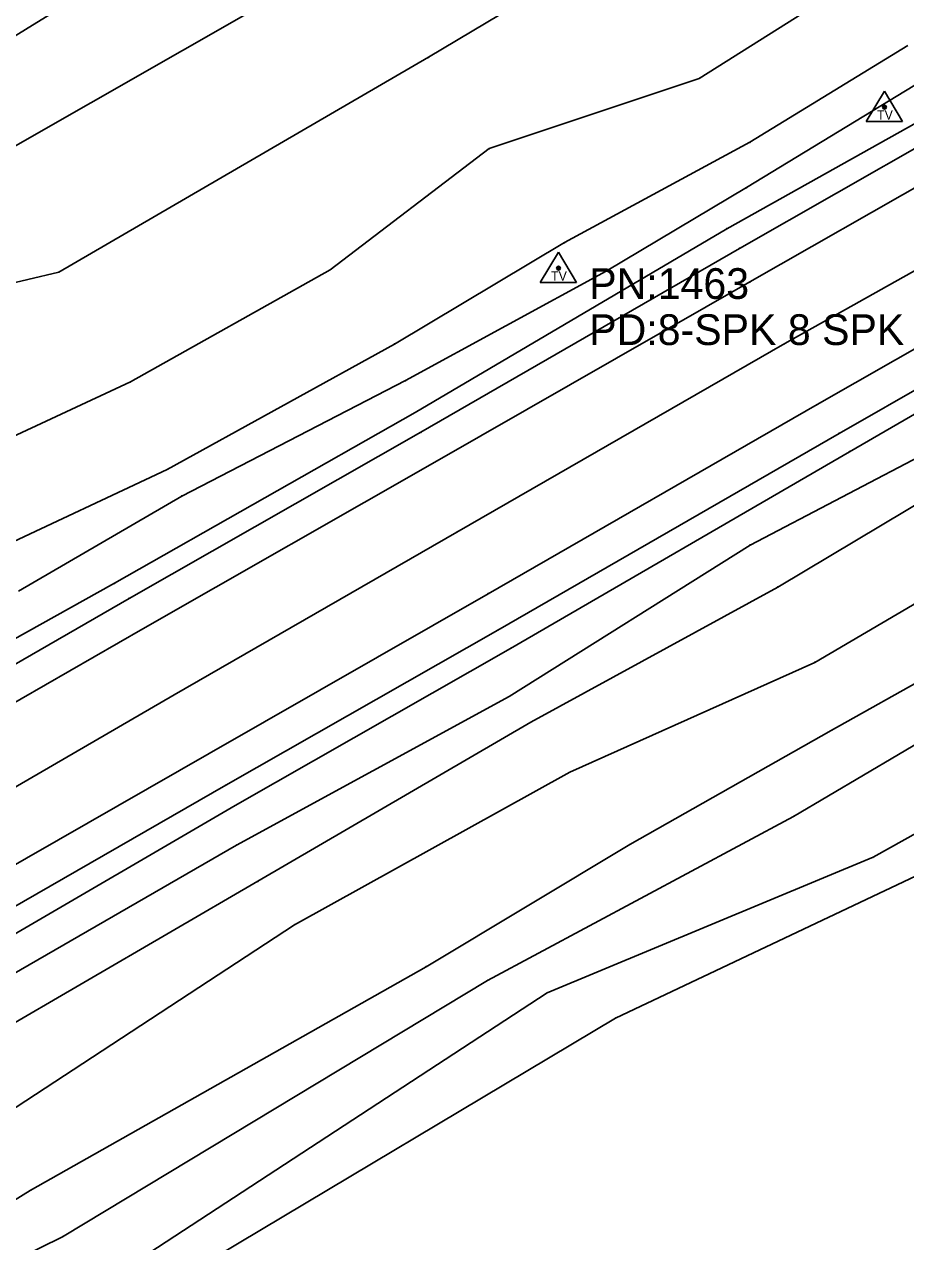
# Model space of a CAD drawing. Extents: x 1419505 to 1434054, y 1956910 to 1968644.
# Drawn here: x 1422395.6 to 1422539.1, y 1958500.2 to 1958698.2 of the extents above; entities that cross this region are included whole.
import ezdxf

# ---------------------------------------------------------------- set-up
doc = ezdxf.new("R2010")
doc.units = 0
for name, color, linetype in [('S_BREAKLINE', 7, 'Continuous'), ('S_DITCHLINE', 7, 'Continuous'), ('S_EDGE_PAVEMENT', 7, 'Continuous'), ('S_GRD_PT_SYM', 7, 'Continuous'), ('S_PAVEMENT_CROWN', 7, 'Continuous'), ('S_RDW_PT_SYM', 7, 'Continuous'), ('S_SECONDARY_CTL', 7, 'Continuous'), ('S_SECONDARY_CTL_ANNOT', 7, 'Continuous'), ('S_SHOULDER', 7, 'Continuous')]:
    doc.layers.add(name, color=color, linetype=linetype)

msp = doc.modelspace()

# ---------------------------------------------------------------- linework, layer by layer
at = {"layer": 'S_BREAKLINE'}
for p, q in [((1422382.7101, 1958689.3782), (1422441.0538, 1958725.3215)), ((1422461.4141, 1958692.8994), (1422515.4536, 1958725.2285)), ((1422390.1545, 1958676.2194), (1422450.1924, 1958710.4926)), ((1422505.461, 1958689.4512), (1422526.6403, 1958702.7961)), ((1422513.7285, 1958679.0625), (1422539.4222, 1958694.7976)), ((1422401.2202, 1958657.9362), (1422461.4141, 1958692.8994)), ((1422509.9403, 1958664.9946), (1422557.0843, 1958691.3403)), ((1422471.2908, 1958678.0405), (1422505.461, 1958689.4512)), ((1422513.1865, 1958671.6841), (1422541.8283, 1958689.1252)), ((1422445.4121, 1958658.3022), (1422471.2908, 1958678.0405)), ((1422483.5336, 1958662.7245), (1422513.7285, 1958679.0625)), ((1422490.309, 1958658.1032), (1422513.1865, 1958671.6841)), ((1422459.229, 1958635.0887), (1422509.9403, 1958664.9946)), ((1422455.8438, 1958646.2244), (1422483.5336, 1958662.7245)), ((1422359.4856, 1958648.0975), (1422401.2202, 1958657.9362)), ((1422412.872, 1958640.073), (1422445.4121, 1958658.3022)), ((1422457.6589, 1958640.283), (1422490.309, 1958658.1032)), ((1422529.9036, 1958628.7053), (1422575.9995, 1958655.405)), ((1422418.8514, 1958625.8221), (1422455.8438, 1958646.2244)), ((1422376.8577, 1958623.2629), (1422412.872, 1958640.073)), ((1422421.2215, 1958621.4938), (1422457.6589, 1958640.283)), ((1422513.7555, 1958613.5103), (1422560.7295, 1958638.1109)), ((1422410.3008, 1958607.2949), (1422459.229, 1958635.0887)), ((1422518.2358, 1958606.6839), (1422563.0037, 1958633.3846)), ((1422474.764, 1958596.7022), (1422529.9036, 1958628.7053)), ((1422391.0466, 1958612.7583), (1422418.8514, 1958625.8221)), ((1422524.2652, 1958594.4251), (1422575.5835, 1958624.449)), ((1422394.6328, 1958606.0288), (1422421.2215, 1958621.4938)), ((1422526.9554, 1958583.3564), (1422582.2199, 1958614.3194)), ((1422474.546, 1958588.8787), (1422513.7555, 1958613.5103)), ((1422359.4726, 1958579.0301), (1422410.3008, 1958607.2949)), ((1422478.0582, 1958584.6984), (1422518.2358, 1958606.6839)), ((1422429.9161, 1958571.1386), (1422474.764, 1958596.7022)), ((1422484.3896, 1958576.5599), (1422524.2652, 1958594.4251)), ((1422430.1541, 1958564.6961), (1422474.546, 1958588.8787)), ((1422433.6193, 1958558.8038), (1422478.0582, 1958584.6984)), ((1422494.1883, 1958564.8072), (1422526.9554, 1958583.3564)), ((1422439.6027, 1958551.7483), (1422484.3896, 1958576.5599)), ((1422379.5428, 1958541.7597), (1422429.9161, 1958571.1386)), ((1422376.5187, 1958533.7862), (1422430.1541, 1958564.6961)), ((1422460.9871, 1958544.9109), (1422494.1883, 1958564.8072)), ((1422379.8909, 1958527.5858), (1422433.6193, 1958558.8038)), ((1422491.8421, 1958536.5513), (1422540.7583, 1958559.6738)), ((1422386.7113, 1958517.1431), (1422439.6027, 1958551.7483)), ((1422396.5669, 1958508.5065), (1422460.9871, 1958544.9109)), ((1422413.8181, 1958490.0183), (1422491.8421, 1958536.5513)), ((1422351.098, 1958480.5897), (1422396.5669, 1958508.5065))]:
    msp.add_line(p, q, dxfattribs=at)
at = {"layer": 'S_DITCHLINE'}
for p, q in [((1422520.832, 1958569.3745), (1422586.0932, 1958607.8579)), ((1422533.7638, 1958562.71), (1422593.1296, 1958595.9822)), ((1422471.0038, 1958542.6787), (1422520.832, 1958569.3745)), ((1422480.6964, 1958540.6546), (1422533.7638, 1958562.71)), ((1422401.8303, 1958500.98), (1422471.0038, 1958542.6787)), ((1422409.7558, 1958494.3216), (1422480.6964, 1958540.6546)), ((1422352.3031, 1958476.6255), (1422401.8303, 1958500.98))]:
    msp.add_line(p, q, dxfattribs=at)
at = {"layer": 'S_EDGE_PAVEMENT'}
for p, q in [((1422513.7115, 1958656.3271), (1422561.5106, 1958683.6458)), ((1422524.6412, 1958636.3678), (1422571.3862, 1958663.0315)), ((1422462.8152, 1958627.2262), (1422513.7115, 1958656.3271)), ((1422471.0978, 1958605.5868), (1422524.6412, 1958636.3678)), ((1422414.9011, 1958599.8904), (1422462.8152, 1958627.2262)), ((1422425.6748, 1958579.5971), (1422471.0978, 1958605.5868)), ((1422363.2818, 1958570.2055), (1422414.9011, 1958599.8904)), ((1422374.5395, 1958550.3272), (1422425.6748, 1958579.5971))]:
    msp.add_line(p, q, dxfattribs=at)
at = {"layer": 'S_GRD_PT_SYM'}
for points in [[(1422461.4141, 1958692.8994), (1422461.4141, 1958692.9494), (1422461.4141, 1958692.8994), (1422461.3641, 1958692.8994), (1422461.4141, 1958692.8994), (1422461.4141, 1958692.8494), (1422461.4141, 1958692.8994), (1422461.4641, 1958692.8994)], [(1422505.461, 1958689.4512), (1422505.461, 1958689.5012), (1422505.461, 1958689.4512), (1422505.411, 1958689.4512), (1422505.461, 1958689.4512), (1422505.461, 1958689.4012), (1422505.461, 1958689.4512), (1422505.511, 1958689.4512)], [(1422471.2908, 1958678.0405), (1422471.2908, 1958678.0905), (1422471.2908, 1958678.0405), (1422471.2408, 1958678.0405), (1422471.2908, 1958678.0405), (1422471.2908, 1958677.9905), (1422471.2908, 1958678.0405), (1422471.3408, 1958678.0405)], [(1422513.7285, 1958679.0625), (1422513.7285, 1958679.1125), (1422513.7285, 1958679.0625), (1422513.6785, 1958679.0625), (1422513.7285, 1958679.0625), (1422513.7285, 1958679.0125), (1422513.7285, 1958679.0625), (1422513.7785, 1958679.0625)], [(1422513.1865, 1958671.6841), (1422513.1865, 1958671.7341), (1422513.1865, 1958671.6841), (1422513.1365, 1958671.6841), (1422513.1865, 1958671.6841), (1422513.1865, 1958671.6341), (1422513.1865, 1958671.6841), (1422513.2365, 1958671.6841)], [(1422509.9403, 1958664.9946), (1422509.9403, 1958665.0446), (1422509.9403, 1958664.9946), (1422509.8903, 1958664.9946), (1422509.9403, 1958664.9946), (1422509.9403, 1958664.9446), (1422509.9403, 1958664.9946), (1422509.9903, 1958664.9946)], [(1422483.5336, 1958662.7245), (1422483.5336, 1958662.7745), (1422483.5336, 1958662.7245), (1422483.4836, 1958662.7245), (1422483.5336, 1958662.7245), (1422483.5336, 1958662.6745), (1422483.5336, 1958662.7245), (1422483.5836, 1958662.7245)], [(1422401.2202, 1958657.9362), (1422401.2202, 1958657.9862), (1422401.2202, 1958657.9362), (1422401.1702, 1958657.9362), (1422401.2202, 1958657.9362), (1422401.2202, 1958657.8862), (1422401.2202, 1958657.9362), (1422401.2702, 1958657.9362)], [(1422445.4121, 1958658.3022), (1422445.4121, 1958658.3522), (1422445.4121, 1958658.3022), (1422445.3621, 1958658.3022), (1422445.4121, 1958658.3022), (1422445.4121, 1958658.2522), (1422445.4121, 1958658.3022), (1422445.4621, 1958658.3022)], [(1422490.309, 1958658.1032), (1422490.309, 1958658.1532), (1422490.309, 1958658.1032), (1422490.259, 1958658.1032), (1422490.309, 1958658.1032), (1422490.309, 1958658.0532), (1422490.309, 1958658.1032), (1422490.359, 1958658.1032)], [(1422455.8438, 1958646.2244), (1422455.8438, 1958646.2744), (1422455.8438, 1958646.2244), (1422455.7938, 1958646.2244), (1422455.8438, 1958646.2244), (1422455.8438, 1958646.1744), (1422455.8438, 1958646.2244), (1422455.8938, 1958646.2244)], [(1422412.872, 1958640.073), (1422412.872, 1958640.123), (1422412.872, 1958640.073), (1422412.822, 1958640.073), (1422412.872, 1958640.073), (1422412.872, 1958640.023), (1422412.872, 1958640.073), (1422412.922, 1958640.073)], [(1422457.6589, 1958640.283), (1422457.6589, 1958640.333), (1422457.6589, 1958640.283), (1422457.6089, 1958640.283), (1422457.6589, 1958640.283), (1422457.6589, 1958640.233), (1422457.6589, 1958640.283), (1422457.7089, 1958640.283)], [(1422459.229, 1958635.0887), (1422459.229, 1958635.1387), (1422459.229, 1958635.0887), (1422459.179, 1958635.0887), (1422459.229, 1958635.0887), (1422459.229, 1958635.0387), (1422459.229, 1958635.0887), (1422459.279, 1958635.0887)], [(1422529.9036, 1958628.7053), (1422529.9036, 1958628.7553), (1422529.9036, 1958628.7053), (1422529.8536, 1958628.7053), (1422529.9036, 1958628.7053), (1422529.9036, 1958628.6553), (1422529.9036, 1958628.7053), (1422529.9536, 1958628.7053)], [(1422418.8514, 1958625.8221), (1422418.8514, 1958625.8721), (1422418.8514, 1958625.8221), (1422418.8014, 1958625.8221), (1422418.8514, 1958625.8221), (1422418.8514, 1958625.7721), (1422418.8514, 1958625.8221), (1422418.9014, 1958625.8221)], [(1422421.2215, 1958621.4938), (1422421.2215, 1958621.5438), (1422421.2215, 1958621.4938), (1422421.1715, 1958621.4938), (1422421.2215, 1958621.4938), (1422421.2215, 1958621.4438), (1422421.2215, 1958621.4938), (1422421.2715, 1958621.4938)], [(1422513.7555, 1958613.5103), (1422513.7555, 1958613.5603), (1422513.7555, 1958613.5103), (1422513.7055, 1958613.5103), (1422513.7555, 1958613.5103), (1422513.7555, 1958613.4603), (1422513.7555, 1958613.5103), (1422513.8055, 1958613.5103)], [(1422410.3008, 1958607.2949), (1422410.3008, 1958607.3449), (1422410.3008, 1958607.2949), (1422410.2508, 1958607.2949), (1422410.3008, 1958607.2949), (1422410.3008, 1958607.2449), (1422410.3008, 1958607.2949), (1422410.3508, 1958607.2949)], [(1422518.2358, 1958606.6839), (1422518.2358, 1958606.7339), (1422518.2358, 1958606.6839), (1422518.1858, 1958606.6839), (1422518.2358, 1958606.6839), (1422518.2358, 1958606.6339), (1422518.2358, 1958606.6839), (1422518.2858, 1958606.6839)], [(1422474.764, 1958596.7022), (1422474.764, 1958596.7522), (1422474.764, 1958596.7022), (1422474.714, 1958596.7022), (1422474.764, 1958596.7022), (1422474.764, 1958596.6522), (1422474.764, 1958596.7022), (1422474.814, 1958596.7022)], [(1422524.2652, 1958594.4251), (1422524.2652, 1958594.4751), (1422524.2652, 1958594.4251), (1422524.2152, 1958594.4251), (1422524.2652, 1958594.4251), (1422524.2652, 1958594.3751), (1422524.2652, 1958594.4251), (1422524.3152, 1958594.4251)], [(1422474.546, 1958588.8787), (1422474.546, 1958588.9287), (1422474.546, 1958588.8787), (1422474.496, 1958588.8787), (1422474.546, 1958588.8787), (1422474.546, 1958588.8287), (1422474.546, 1958588.8787), (1422474.596, 1958588.8787)], [(1422478.0582, 1958584.6984), (1422478.0582, 1958584.7484), (1422478.0582, 1958584.6984), (1422478.0082, 1958584.6984), (1422478.0582, 1958584.6984), (1422478.0582, 1958584.6484), (1422478.0582, 1958584.6984), (1422478.1082, 1958584.6984)], [(1422526.9554, 1958583.3564), (1422526.9554, 1958583.4064), (1422526.9554, 1958583.3564), (1422526.9054, 1958583.3564), (1422526.9554, 1958583.3564), (1422526.9554, 1958583.3064), (1422526.9554, 1958583.3564), (1422527.0054, 1958583.3564)], [(1422484.3896, 1958576.5599), (1422484.3896, 1958576.6099), (1422484.3896, 1958576.5599), (1422484.3396, 1958576.5599), (1422484.3896, 1958576.5599), (1422484.3896, 1958576.5099), (1422484.3896, 1958576.5599), (1422484.4396, 1958576.5599)], [(1422429.9161, 1958571.1386), (1422429.9161, 1958571.1886), (1422429.9161, 1958571.1386), (1422429.8661, 1958571.1386), (1422429.9161, 1958571.1386), (1422429.9161, 1958571.0886), (1422429.9161, 1958571.1386), (1422429.9661, 1958571.1386)], [(1422520.832, 1958569.3745), (1422520.832, 1958569.4245), (1422520.832, 1958569.3745), (1422520.782, 1958569.3745), (1422520.832, 1958569.3745), (1422520.832, 1958569.3245), (1422520.832, 1958569.3745), (1422520.882, 1958569.3745)], [(1422430.1541, 1958564.6961), (1422430.1541, 1958564.7461), (1422430.1541, 1958564.6961), (1422430.1041, 1958564.6961), (1422430.1541, 1958564.6961), (1422430.1541, 1958564.6461), (1422430.1541, 1958564.6961), (1422430.2041, 1958564.6961)], [(1422494.1883, 1958564.8072), (1422494.1883, 1958564.8572), (1422494.1883, 1958564.8072), (1422494.1383, 1958564.8072), (1422494.1883, 1958564.8072), (1422494.1883, 1958564.7572), (1422494.1883, 1958564.8072), (1422494.2383, 1958564.8072)], [(1422533.7638, 1958562.71), (1422533.7638, 1958562.76), (1422533.7638, 1958562.71), (1422533.7138, 1958562.71), (1422533.7638, 1958562.71), (1422533.7638, 1958562.66), (1422533.7638, 1958562.71), (1422533.8138, 1958562.71)], [(1422433.6193, 1958558.8038), (1422433.6193, 1958558.8538), (1422433.6193, 1958558.8038), (1422433.5693, 1958558.8038), (1422433.6193, 1958558.8038), (1422433.6193, 1958558.7538), (1422433.6193, 1958558.8038), (1422433.6693, 1958558.8038)], [(1422439.6027, 1958551.7483), (1422439.6027, 1958551.7983), (1422439.6027, 1958551.7483), (1422439.5527, 1958551.7483), (1422439.6027, 1958551.7483), (1422439.6027, 1958551.6983), (1422439.6027, 1958551.7483), (1422439.6527, 1958551.7483)], [(1422460.9871, 1958544.9109), (1422460.9871, 1958544.9609), (1422460.9871, 1958544.9109), (1422460.9371, 1958544.9109), (1422460.9871, 1958544.9109), (1422460.9871, 1958544.8609), (1422460.9871, 1958544.9109), (1422461.0371, 1958544.9109)], [(1422471.0038, 1958542.6787), (1422471.0038, 1958542.7287), (1422471.0038, 1958542.6787), (1422470.9538, 1958542.6787), (1422471.0038, 1958542.6787), (1422471.0038, 1958542.6287), (1422471.0038, 1958542.6787), (1422471.0538, 1958542.6787)], [(1422480.6964, 1958540.6546), (1422480.6964, 1958540.7046), (1422480.6964, 1958540.6546), (1422480.6464, 1958540.6546), (1422480.6964, 1958540.6546), (1422480.6964, 1958540.6046), (1422480.6964, 1958540.6546), (1422480.7464, 1958540.6546)], [(1422491.8421, 1958536.5513), (1422491.8421, 1958536.6013), (1422491.8421, 1958536.5513), (1422491.7921, 1958536.5513), (1422491.8421, 1958536.5513), (1422491.8421, 1958536.5013), (1422491.8421, 1958536.5513), (1422491.8921, 1958536.5513)], [(1422396.5669, 1958508.5065), (1422396.5669, 1958508.5565), (1422396.5669, 1958508.5065), (1422396.5169, 1958508.5065), (1422396.5669, 1958508.5065), (1422396.5669, 1958508.4565), (1422396.5669, 1958508.5065), (1422396.6169, 1958508.5065)], [(1422401.8303, 1958500.98), (1422401.8303, 1958501.03), (1422401.8303, 1958500.98), (1422401.7803, 1958500.98), (1422401.8303, 1958500.98), (1422401.8303, 1958500.93), (1422401.8303, 1958500.98), (1422401.8803, 1958500.98)]]:
    msp.add_lwpolyline(points, dxfattribs=at)
at = {"layer": 'S_PAVEMENT_CROWN'}
for p, q in [((1422519.3899, 1958646.2924), (1422565.7189, 1958672.3091)), ((1422466.0314, 1958615.6224), (1422519.3899, 1958646.2924)), ((1422419.9995, 1958589.1487), (1422466.0314, 1958615.6224)), ((1422369.2062, 1958559.7138), (1422419.9995, 1958589.1487))]:
    msp.add_line(p, q, dxfattribs=at)
at = {"layer": 'S_RDW_PT_SYM'}
for points in [[(1422512.0114, 1958661.7954), (1422512.0114, 1958661.8454), (1422512.0114, 1958661.7954), (1422511.9614, 1958661.7954), (1422512.0114, 1958661.7954), (1422512.0114, 1958661.7454), (1422512.0114, 1958661.7954), (1422512.0614, 1958661.7954)], [(1422513.7115, 1958656.3271), (1422513.7115, 1958656.3771), (1422513.7115, 1958656.3271), (1422513.6615, 1958656.3271), (1422513.7115, 1958656.3271), (1422513.7115, 1958656.2771), (1422513.7115, 1958656.3271), (1422513.7615, 1958656.3271)], [(1422519.3899, 1958646.2924), (1422519.3899, 1958646.3424), (1422519.3899, 1958646.2924), (1422519.3399, 1958646.2924), (1422519.3899, 1958646.2924), (1422519.3899, 1958646.2424), (1422519.3899, 1958646.2924), (1422519.4399, 1958646.2924)], [(1422524.6412, 1958636.3678), (1422524.6412, 1958636.4178), (1422524.6412, 1958636.3678), (1422524.5912, 1958636.3678), (1422524.6412, 1958636.3678), (1422524.6412, 1958636.3178), (1422524.6412, 1958636.3678), (1422524.6912, 1958636.3678)], [(1422460.1661, 1958631.8705), (1422460.1661, 1958631.9205), (1422460.1661, 1958631.8705), (1422460.1161, 1958631.8705), (1422460.1661, 1958631.8705), (1422460.1661, 1958631.8205), (1422460.1661, 1958631.8705), (1422460.2161, 1958631.8705)], [(1422528.2315, 1958631.6965), (1422528.2315, 1958631.7465), (1422528.2315, 1958631.6965), (1422528.1815, 1958631.6965), (1422528.2315, 1958631.6965), (1422528.2315, 1958631.6465), (1422528.2315, 1958631.6965), (1422528.2815, 1958631.6965)], [(1422462.8152, 1958627.2262), (1422462.8152, 1958627.2762), (1422462.8152, 1958627.2262), (1422462.7652, 1958627.2262), (1422462.8152, 1958627.2262), (1422462.8152, 1958627.1762), (1422462.8152, 1958627.2262), (1422462.8652, 1958627.2262)], [(1422466.0314, 1958615.6224), (1422466.0314, 1958615.6724), (1422466.0314, 1958615.6224), (1422465.9814, 1958615.6224), (1422466.0314, 1958615.6224), (1422466.0314, 1958615.5724), (1422466.0314, 1958615.6224), (1422466.0814, 1958615.6224)], [(1422412.647, 1958604.8277), (1422412.647, 1958604.8777), (1422412.647, 1958604.8277), (1422412.597, 1958604.8277), (1422412.647, 1958604.8277), (1422412.647, 1958604.7777), (1422412.647, 1958604.8277), (1422412.697, 1958604.8277)], [(1422471.0978, 1958605.5868), (1422471.0978, 1958605.6368), (1422471.0978, 1958605.5868), (1422471.0478, 1958605.5868), (1422471.0978, 1958605.5868), (1422471.0978, 1958605.5368), (1422471.0978, 1958605.5868), (1422471.1478, 1958605.5868)], [(1422414.9011, 1958599.8904), (1422414.9011, 1958599.9404), (1422414.9011, 1958599.8904), (1422414.8511, 1958599.8904), (1422414.9011, 1958599.8904), (1422414.9011, 1958599.8404), (1422414.9011, 1958599.8904), (1422414.9511, 1958599.8904)], [(1422472.6899, 1958599.6904), (1422472.6899, 1958599.7404), (1422472.6899, 1958599.6904), (1422472.6399, 1958599.6904), (1422472.6899, 1958599.6904), (1422472.6899, 1958599.6404), (1422472.6899, 1958599.6904), (1422472.7399, 1958599.6904)], [(1422419.9995, 1958589.1487), (1422419.9995, 1958589.1987), (1422419.9995, 1958589.1487), (1422419.9495, 1958589.1487), (1422419.9995, 1958589.1487), (1422419.9995, 1958589.0987), (1422419.9995, 1958589.1487), (1422420.0495, 1958589.1487)], [(1422425.6748, 1958579.5971), (1422425.6748, 1958579.6471), (1422425.6748, 1958579.5971), (1422425.6248, 1958579.5971), (1422425.6748, 1958579.5971), (1422425.6748, 1958579.5471), (1422425.6748, 1958579.5971), (1422425.7248, 1958579.5971)], [(1422428.376, 1958574.4508), (1422428.376, 1958574.5008), (1422428.376, 1958574.4508), (1422428.326, 1958574.4508), (1422428.376, 1958574.4508), (1422428.376, 1958574.4008), (1422428.376, 1958574.4508), (1422428.426, 1958574.4508)]]:
    msp.add_lwpolyline(points, dxfattribs=at)
at = {"layer": 'S_SECONDARY_CTL'}
for p, q in [((1422535.6259, 1958687.379), (1422532.6159, 1958682.4251)), ((1422535.6259, 1958687.379), (1422538.5732, 1958682.4251)), ((1422532.6159, 1958682.4251), (1422538.5732, 1958682.4251)), ((1422482.5605, 1958661.1793), (1422479.5505, 1958656.2254)), ((1422482.5605, 1958661.1793), (1422485.5078, 1958656.2254)), ((1422479.5505, 1958656.2254), (1422485.5078, 1958656.2254))]:
    msp.add_line(p, q, dxfattribs=at)
for centre, radius in [((1422535.6259, 1958684.7689), 0.3111), ((1422535.6259, 1958684.7689), 0.1827), ((1422535.6259, 1958684.7689), 0.1033), ((1422482.5605, 1958658.5692), 0.3111), ((1422482.5605, 1958658.5692), 0.1827), ((1422482.5605, 1958658.5692), 0.1033)]:
    msp.add_circle(centre, radius, dxfattribs=at)
at = {"layer": 'S_SHOULDER'}
for p, q in [((1422512.0114, 1958661.7954), (1422559.1074, 1958688.6632)), ((1422460.1661, 1958631.8705), (1422512.0114, 1958661.7954)), ((1422528.2315, 1958631.6965), (1422574.7325, 1958658.1932)), ((1422412.647, 1958604.8277), (1422460.1661, 1958631.8705)), ((1422472.6899, 1958599.6904), (1422528.2315, 1958631.6965)), ((1422360.6196, 1958574.8538), (1422412.647, 1958604.8277)), ((1422428.376, 1958574.4508), (1422472.6899, 1958599.6904)), ((1422377.3217, 1958545.1219), (1422428.376, 1958574.4508))]:
    msp.add_line(p, q, dxfattribs=at)

# ---------------------------------------------------------------- texts
at = {"layer": 'S_SECONDARY_CTL'}
for p in [(1422534.4212, 1958682.7576), (1422481.3558, 1958656.5579)]:
    msp.add_text('TV', height=1.5, rotation=360, dxfattribs=at).set_placement(p)
at = {"layer": 'S_SECONDARY_CTL_ANNOT'}
for s, p in [('PN:1463', (1422487.5605, 1958653.5692)), ('PD:8-SPK 8 SPK', (1422487.5605, 1958646.0692))]:
    msp.add_text(s, height=5, dxfattribs=at).set_placement(p)

doc.saveas('drawing.dxf')
